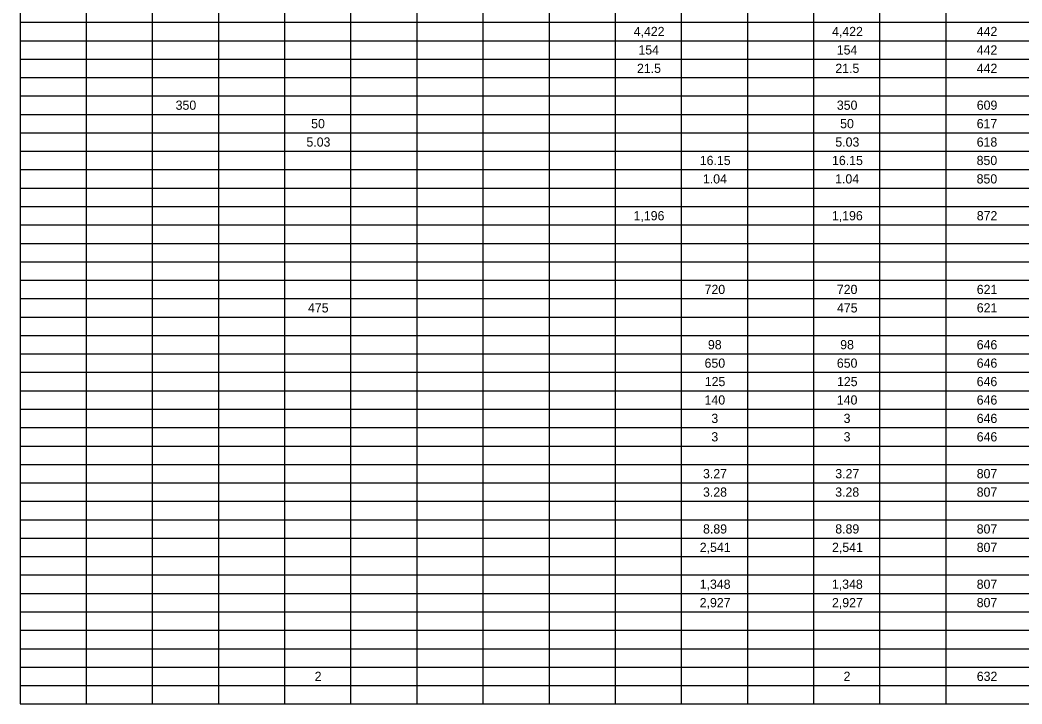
# Model space of a CAD drawing. Extents: x -32.9 to 34, y 0 to 22.
# Drawn here: x -32.94 to -17.72, y 0.5 to 10.89 of the extents above; entities that cross this region are included whole.
import ezdxf

# ---------------------------------------------------------------- set-up
doc = ezdxf.new("R2010")
doc.units = 0
doc.layers.add('SH_Text', color=7, linetype='Continuous')

msp = doc.modelspace()

# ---------------------------------------------------------------- linework, layer by layer
at = {"layer": 'SH_Text'}
for p, q in [((-32.943, 21.5), (-32.943, 0.5)), ((-20.886, 21.5), (-20.886, 0.5)), ((-18.877, 21.5), (-18.877, 0.5)), ((-31.938, 20.94), (-31.938, 0.5)), ((-30.933, 20.94), (-30.933, 0.5)), ((-29.929, 20.94), (-29.929, 0.5)), ((-28.924, 20.94), (-28.924, 0.5)), ((-27.919, 20.94), (-27.919, 0.5)), ((-26.915, 20.94), (-26.915, 0.5)), ((-25.91, 20.94), (-25.91, 0.5)), ((-24.905, 20.94), (-24.905, 0.5)), ((-23.9, 20.94), (-23.9, 0.5)), ((-22.896, 20.94), (-22.896, 0.5)), ((-21.891, 20.94), (-21.891, 0.5)), ((-19.882, 20.94), (-19.882, 0.5)), ((-32.943, 10.86), (-2.439, 10.86)), ((-32.943, 10.58), (-2.439, 10.58)), ((-32.943, 10.3), (-2.439, 10.3)), ((-32.943, 10.02), (-2.439, 10.02)), ((-32.943, 9.74), (-2.439, 9.74)), ((-32.943, 9.46), (-2.439, 9.46)), ((-32.943, 9.18), (-2.439, 9.18)), ((-32.943, 8.9), (-2.439, 8.9)), ((-32.943, 8.62), (-2.439, 8.62)), ((-32.943, 8.34), (-2.439, 8.34)), ((-32.943, 8.06), (-2.439, 8.06)), ((-32.943, 7.78), (-2.439, 7.78)), ((-32.943, 7.5), (-2.439, 7.5)), ((-32.943, 7.22), (-2.439, 7.22)), ((-32.943, 6.94), (-2.439, 6.94)), ((-32.943, 6.66), (-2.439, 6.66)), ((-32.943, 6.38), (-2.439, 6.38)), ((-32.943, 6.1), (-2.439, 6.1)), ((-32.943, 5.82), (-2.439, 5.82)), ((-32.943, 5.54), (-2.439, 5.54)), ((-32.943, 5.26), (-2.439, 5.26)), ((-32.943, 4.98), (-2.439, 4.98)), ((-32.943, 4.7), (-2.439, 4.7)), ((-32.943, 4.42), (-2.439, 4.42)), ((-32.943, 4.14), (-2.439, 4.14)), ((-32.943, 3.86), (-2.439, 3.86)), ((-32.943, 3.58), (-2.439, 3.58)), ((-32.943, 3.3), (-2.439, 3.3)), ((-32.943, 3.02), (-2.439, 3.02)), ((-32.943, 2.74), (-2.439, 2.74)), ((-32.943, 2.46), (-2.439, 2.46)), ((-32.943, 2.18), (-2.439, 2.18)), ((-32.943, 1.9), (-2.439, 1.9)), ((-32.943, 1.62), (-2.439, 1.62)), ((-32.943, 1.34), (-2.439, 1.34)), ((-32.943, 1.06), (-2.439, 1.06)), ((-32.943, 0.78), (-2.439, 0.78)), ((-32.943, 0.5), (-2.439, 0.5))]:
    msp.add_line(p, q, dxfattribs=at)

# ---------------------------------------------------------------- texts
for s, p in [('4,422', (-23.618, 10.65)), ('4,422', (-20.604, 10.65)), ('442', (-18.405, 10.65)), ('154', (-23.546, 10.37)), ('154', (-20.532, 10.37)), ('442', (-18.405, 10.37)), ('21.5', (-23.568, 10.09)), ('21.5', (-20.554, 10.09)), ('442', (-18.405, 10.09)), ('350', (-30.578, 9.53)), ('350', (-20.531, 9.53)), ('609', (-18.405, 9.53)), ('50', (-28.519, 9.25)), ('50', (-20.481, 9.25)), ('617', (-18.406, 9.25)), ('5.03', (-28.591, 8.97)), ('5.03', (-20.554, 8.97)), ('618', (-18.406, 8.97)), ('16.15', (-22.614, 8.69)), ('16.15', (-20.604, 8.69)), ('850', (-18.407, 8.69)), ('1.04', (-22.566, 8.41)), ('1.04', (-20.557, 8.41)), ('850', (-18.407, 8.41)), ('1,196', (-23.62, 7.85)), ('1,196', (-20.606, 7.85)), ('872', (-18.405, 7.85)), ('720', (-22.541, 6.73)), ('720', (-20.531, 6.73)), ('621', (-18.405, 6.73)), ('475', (-28.567, 6.45)), ('475', (-20.529, 6.45)), ('621', (-18.405, 6.45)), ('98', (-22.49, 5.89)), ('98', (-20.48, 5.89)), ('646', (-18.406, 5.89)), ('650', (-22.541, 5.61)), ('650', (-20.531, 5.61)), ('646', (-18.406, 5.61)), ('125', (-22.538, 5.33)), ('125', (-20.529, 5.33)), ('646', (-18.406, 5.33)), ('140', (-22.541, 5.05)), ('140', (-20.531, 5.05)), ('646', (-18.406, 5.05)), ('3', (-22.438, 4.77)), ('3', (-20.428, 4.77)), ('646', (-18.406, 4.77)), ('3', (-22.438, 4.49)), ('3', (-20.428, 4.49)), ('646', (-18.406, 4.49)), ('3.27', (-22.565, 3.93)), ('3.27', (-20.555, 3.93)), ('807', (-18.406, 3.93)), ('3.28', (-22.565, 3.65)), ('3.28', (-20.556, 3.65)), ('807', (-18.406, 3.65)), ('8.89', (-22.564, 3.09)), ('8.89', (-20.555, 3.09)), ('807', (-18.406, 3.09)), ('2,541', (-22.614, 2.81)), ('2,541', (-20.604, 2.81)), ('807', (-18.406, 2.81)), ('1,348', (-22.615, 2.25)), ('1,348', (-20.606, 2.25)), ('807', (-18.406, 2.25)), ('2,927', (-22.615, 1.97)), ('2,927', (-20.605, 1.97)), ('807', (-18.406, 1.97)), ('2', (-28.466, 0.85)), ('2', (-20.429, 0.85)), ('632', (-18.405, 0.85))]:
    msp.add_text(s, height=0.14, dxfattribs=at).set_placement(p)

doc.saveas('drawing.dxf')
